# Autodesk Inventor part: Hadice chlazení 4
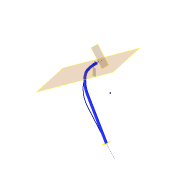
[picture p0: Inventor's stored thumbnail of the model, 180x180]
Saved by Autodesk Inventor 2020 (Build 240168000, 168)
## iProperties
Created: 2025-04
Part Number: Hadice chlazení 4
Material: Polyetylen, S nízkou hustotou
Document SubType Name: Modeling
Designer: doma
Density: 0.894 g/cm^3
Appearance: Modrá – nástěnná malba – lesklá
Mass: 8.78182 g
Surface Area: 197.028 cm^2
Volume: 9.82307 cm^3
Author: doma
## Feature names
1. Tažení3
2. Tažení4
## Parameters: d6 = 5 mm, d12 = 8 mm, d13 = 0, d14 = 0, d15 = 0, d16 = 0
